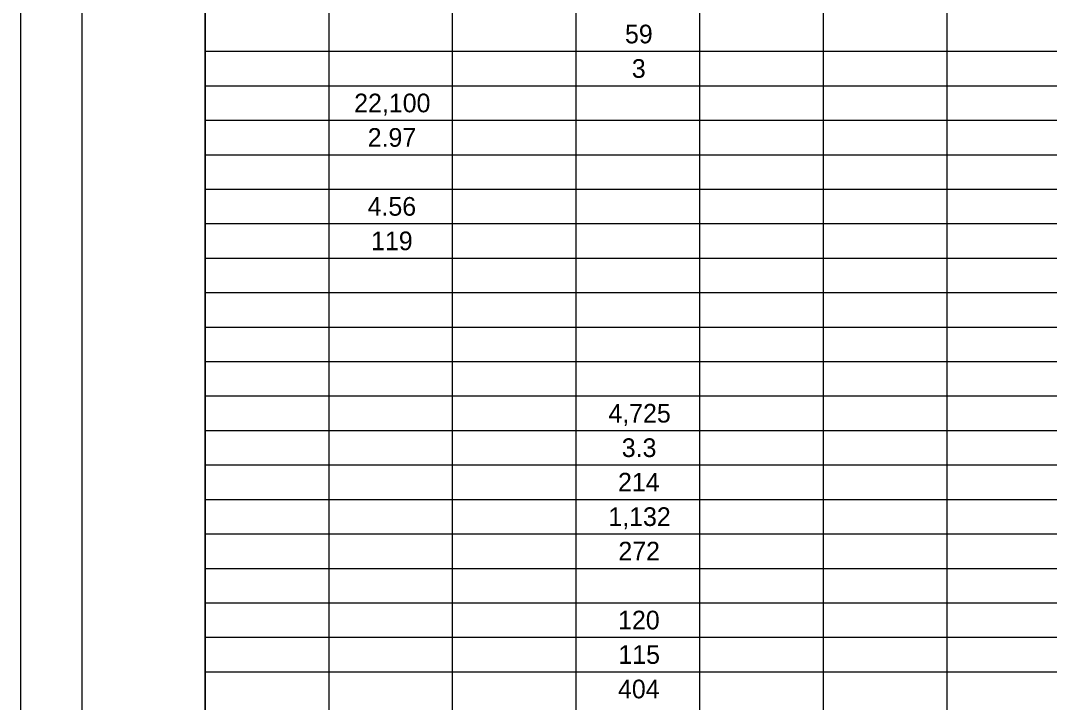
# Model space of a CAD drawing. Extents: x 0 to 34, y 0 to 22.
# Drawn here: x 0 to 8.36, y 10.89 to 16.43 of the extents above; entities that cross this region are included whole.
import ezdxf

# ---------------------------------------------------------------- set-up
doc = ezdxf.new("R2010")
doc.units = 0
for name, color, linetype in [('Default', 7, 'Continuous'), ('SH_Border', 7, 'Continuous'), ('SH_Cut_Line', 7, 'Continuous')]:
    doc.layers.add(name, color=color, linetype=linetype)

msp = doc.modelspace()

# ---------------------------------------------------------------- linework, layer by layer
at = {"layer": 'Default'}
for p, q in [((1.5, 21.5), (1.5, 0.5)), ((2.5047, 20.94), (2.5047, 0.5)), ((3.5094, 20.94), (3.5094, 0.5)), ((4.5141, 20.94), (4.5141, 0.5)), ((5.5188, 20.94), (5.5188, 0.5)), ((6.5235, 20.94), (6.5235, 0.5)), ((7.5282, 20.94), (7.5282, 0.5)), ((1.5, 16.18), (32.0035, 16.18)), ((1.5, 15.9), (32.0035, 15.9)), ((1.5, 15.62), (32.0035, 15.62)), ((1.5, 15.34), (32.0035, 15.34)), ((1.5, 15.06), (32.0035, 15.06)), ((1.5, 14.78), (32.0035, 14.78)), ((1.5, 14.5), (32.0035, 14.5)), ((1.5, 14.22), (32.0035, 14.22)), ((1.5, 13.94), (32.0035, 13.94)), ((1.5, 13.66), (32.0035, 13.66)), ((1.5, 13.38), (32.0035, 13.38)), ((1.5, 13.1), (32.0035, 13.1)), ((1.5, 12.82), (32.0035, 12.82)), ((1.5, 12.54), (32.0035, 12.54)), ((1.5, 12.26), (32.0035, 12.26)), ((1.5, 11.98), (32.0035, 11.98)), ((1.5, 11.7), (32.0035, 11.7)), ((1.5, 11.42), (32.0035, 11.42)), ((1.5, 11.14), (32.0035, 11.14))]:
    msp.add_line(p, q, dxfattribs=at)
at = {"layer": 'SH_Border'}
for points in [[(0.5, 21.5), (1.5, 21.5), (1.5, 0.5), (0.5, 0.5)], [(1.5, 21.5), (33.5, 21.5), (33.5, 0.5), (1.5, 0.5)]]:
    msp.add_lwpolyline(points, close=True, dxfattribs=at)
at = {"layer": 'SH_Cut_Line'}
msp.add_lwpolyline([(0, 0), (34, 0), (34, 22), (0, 22)], close=True, dxfattribs=at)

# ---------------------------------------------------------------- texts
at = {"layer": 'Default'}
for s, height, p in [('59', 0.15153, (4.9131, 16.2442)), ('3', 0.1515, (4.9686, 15.9642)), ('22,100', 0.15153, (2.7118, 15.6842)), ('2.97', 0.15153, (2.8216, 15.4042)), ('4.56', 0.15153, (2.8209, 14.8442)), ('119', 0.15153, (2.8492, 14.5642)), ('4,725', 0.15153, (4.7782, 13.1642)), ('3.3', 0.15153, (4.887, 12.8842)), ('214', 0.15153, (4.8563, 12.6042)), ('1,132', 0.15153, (4.7779, 12.3242)), ('272', 0.15153, (4.8592, 12.0442)), ('120', 0.15153, (4.8569, 11.4842)), ('115', 0.15153, (4.8595, 11.2042)), ('404', 0.15153, (4.8563, 10.9242))]:
    msp.add_text(s, height=height, dxfattribs=at).set_placement(p)

doc.saveas('drawing.dxf')
